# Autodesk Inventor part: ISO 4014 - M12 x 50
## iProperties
Created: 2007-05
Part Number: ISO 4014 - M12 x 50
Material: Steel, Mild
Description: Hex-Head Bolt
Vendor: Autodesk Inc.
Document SubType Name: Modeling
Standard: ISO 4014
Designer: kurs1
Standards Organization: ISO
Language: en-US
Size Designation: M12 x 50
Categories: <MemberInstance Version="R10.0.0"><Categories><Category DisplayName="Fasteners" InternalName="e4da775c-781d-43d5-af7c-5136215cf5a6" Mnemonic="FSTN"><Category Di
Density: 1 g/cm^3
Author: kurs1
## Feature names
1. Body [Revolution]
2. Head [Extrusion]
3. Chamfer1 [Revolution]
4. Chamfer2
